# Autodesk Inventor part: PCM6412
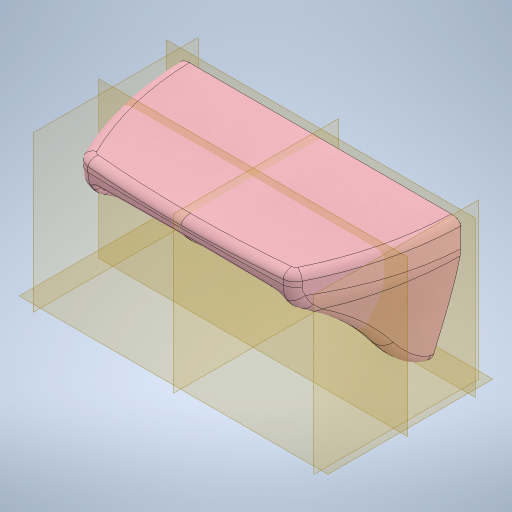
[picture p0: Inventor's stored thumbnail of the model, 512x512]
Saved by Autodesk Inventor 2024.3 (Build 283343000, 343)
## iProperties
Created: 2024-11
Part Number: PCM6412
Material: Generic
Document SubType Name: Modeling
Designer: Brian.Thangei
Density: 1 g/cm^3
Appearance: Default
Project: RYNO
Description: WALL DESK
Author: Brian.Thangei
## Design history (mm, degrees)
derived "PCM6412 - Ryno Wall Desk.iam"
workplane "Work Plane1"
workplane "Work Plane2"
workplane "Work Plane3"
body "Solid1"
node "Ryno Wall Desk (Simplified).ipt:1"
node "PCM6412 - Ryno Wall Desk.iam_Bodies"
other parameters: "d1" = 289
